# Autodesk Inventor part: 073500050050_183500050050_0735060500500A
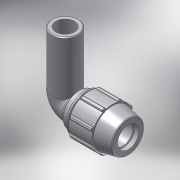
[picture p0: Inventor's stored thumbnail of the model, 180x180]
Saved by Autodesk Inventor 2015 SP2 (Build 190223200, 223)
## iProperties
Created: 2017-02
Part Number: 073500050050_183500050050_0735060500500A
Material: PVC-Piping
Description: PLASSON 90° ELBOW ADAPTOR 50-50
Document SubType Name: Modeling
Designer: KIM
Mass: 92.6774 g
Surface Area: 199.44 cm^2
Volume: 66.1981 cm^3
Density: 1.4 g/cm^3
Appearance: Smooth - White
Author: KIM
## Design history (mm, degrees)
derived "07350.ipt"
feature "Solid1::07350.ipt"
tag "TaggingFeature1"
body "Solid1"
other parameters: "d4" = 11.33333, "d5" = 34, "d7" = 96, "d11" = 4.53333, "d13" = 120 deg, "d15" = 12 deg, "d16" = 83.52, "d18" = 2.5, "d19" = 35 deg, "d20" = 17.5 deg, "d21" = 89.28, "d23" = 0, "d25" = 360 deg, "d27" = 1.92, "d33" = 1, "d42" = 50.32, "d43" = 2.88, "d46" = 1.5, "d51" = 136, "d68" = 4.53333, "d76" = 35, "d80" = 1.5, "d91" = 72, "d93" = 93, "d95" = 35, "d96" = 11.33333, "d97" = 50 deg, "d98" = 72, "d99" = 0, "d100" = 0, "E_" = 96, "A_" = 136, "l_" = 93
